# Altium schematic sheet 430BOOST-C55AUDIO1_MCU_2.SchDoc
size A4
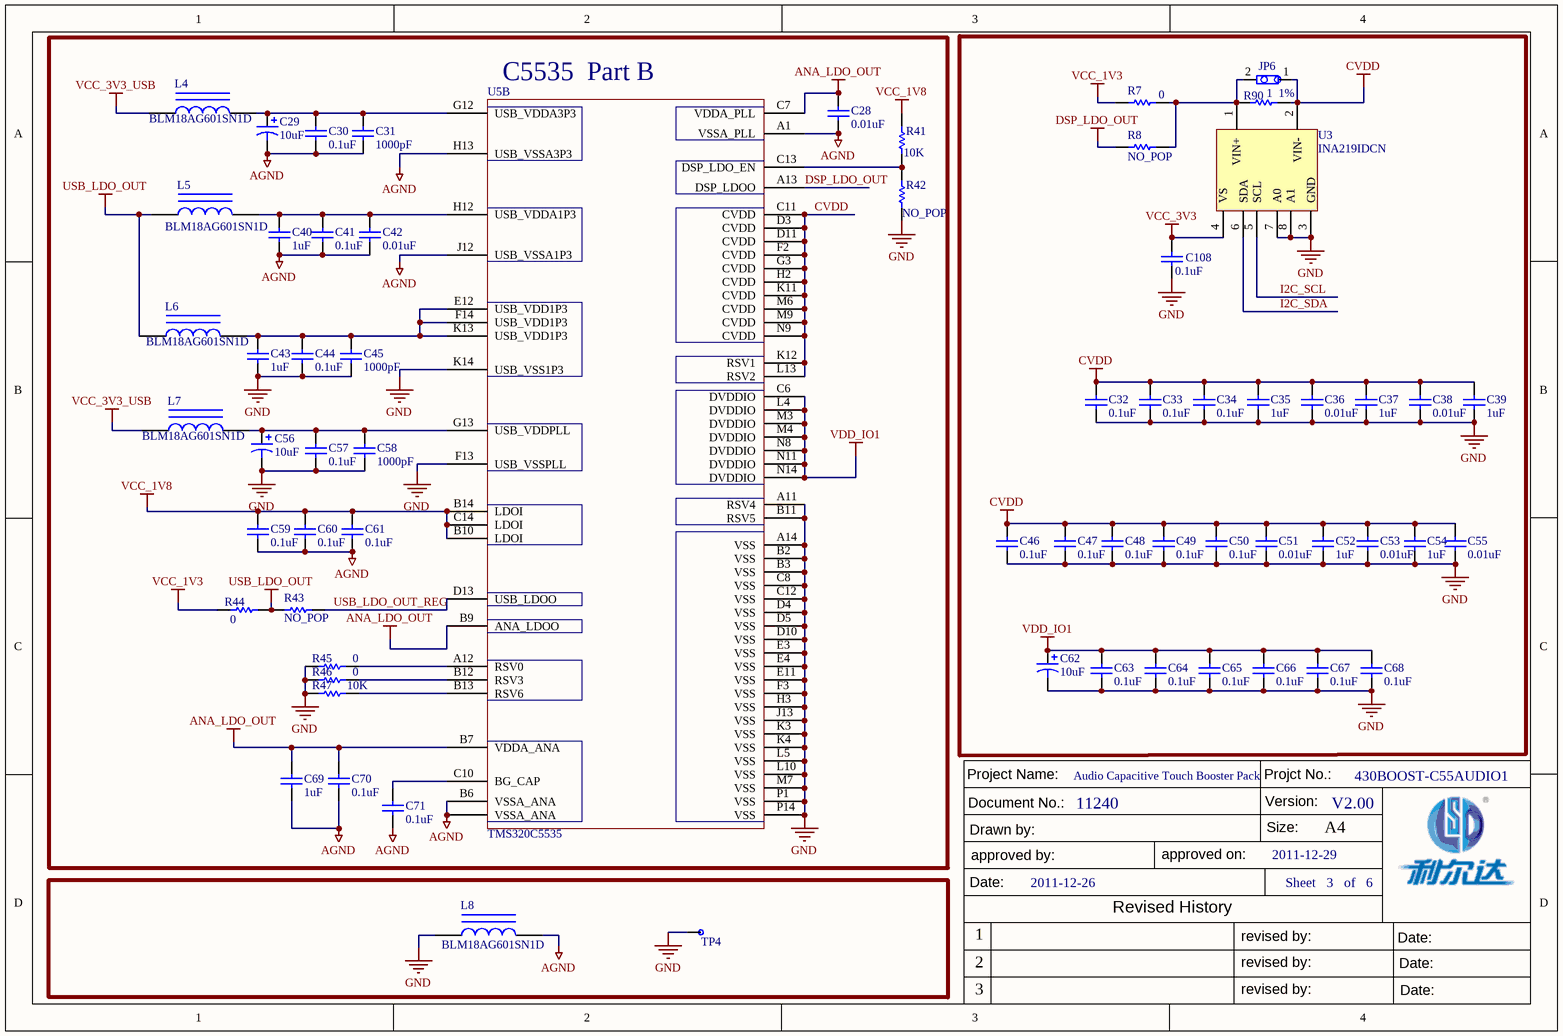
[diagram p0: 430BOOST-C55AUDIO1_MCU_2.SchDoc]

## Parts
C28  0.01uF  [0402-C]
C29  10uF  [0805-C]
C30  0.1uF  [0402-C]
C31  1000pF  [0402-C]
C32  0.1uF  [0402-C]
C33  0.1uF  [0402-C]
C34  0.1uF  [0402-C]
C35  1uF  [0603-C]
C36  0.01uF  [0402-C]
C37  1uF  [0603-C]
C38  0.01uF  [0402-C]
C39  1uF  [0603-C]
C40  1uF  [0603-C]
C41  0.1uF  [0402-C]
C42  0.01uF  [0402-C]
C43  1uF  [0603-C]
C44  0.1uF  [0402-C]
C45  1000pF  [0402-C]
C46  0.1uF  [0402-C]
C47  0.1uF  [0402-C]
C48  0.1uF  [0402-C]
C49  0.1uF  [0402-C]
C50  0.1uF  [0402-C]
C51  0.01uF  [0402-C]
C52  1uF  [0603-C]
C53  0.01uF  [0402-C]
C54  1uF  [0603-C]
C55  0.01uF  [0402-C]
C56  10uF  [0805-C]
C57  0.1uF  [0402-C]
C58  1000pF  [0402-C]
C59  0.1uF  [0402-C]
C60  0.1uF  [0402-C]
C61  0.1uF  [0402-C]
C62  10uF  [0805-C]
C63  0.1uF  [0402-C]
C64  0.1uF  [0402-C]
C65  0.1uF  [0402-C]
C66  0.1uF  [0402-C]
C67  0.1uF  [0402-C]
C68  0.1uF  [0402-C]
C69  1uF  [0603-C]
C70  0.1uF  [0402-C]
C71  0.1uF  [0402-C]
C108  0.1uF  [0402-C]
JP6  (no value)  [SIP2-2.54]
L4  BLM18AG601SN1D  [0603-L]
L5  BLM18AG601SN1D  [0603-L]
L6  BLM18AG601SN1D  [0603-L]
L7  BLM18AG601SN1D  [0603-L]
L8  BLM18AG601SN1D  [0603-L]
R7  0  [0402-R]
R8  NO_POP  [0402-R]
R41  10K  [0402-R]
R42  NO_POP  [0402-R]
R43  NO_POP  [0402-R]
R44  0  [0402-R]
R45  0  [0402-R]
R46  0  [0402-R]
R47  10K  [0402-R]
R90  1  1%  [0402-R]
TP4  GND  [SIP1-TEST]  (value not drawn)
U3  INA219IDCN  [SOT-23-8P]
U5  TMS320C5535  [BGA-N144-0.8MM]  (part B of 2)

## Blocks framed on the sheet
C5535  Part B: C28-C31 C40-C45 C56-C61 C69-C71 L4-L7 R41-R47 U5

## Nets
AGND: C28.1 C29.2 C30.1 C31.1 C40.1 C41.1 C42.1 C59.1 C60.1 C61.1 C69.1 C70.1 C71.1 L8.2 U5.?1(VSSA_ANA) U5.A1(VSSA_PLL) U5.B6(VSSA_ANA) U5.H13(USB_VSSA3P3) U5.J12(USB_VSSA1P3)
ANA_LDO_OUT: C28.2 C69.2 C70.2 U5.B7(VDDA_ANA) U5.B9(ANA_LDOO) U5.C7(VDDA_PLL)
CVDD: C32.2 C33.2 C34.2 C35.2 C36.2 C37.2 C38.2 C39.2 C46.2 C47.2 C48.2 C49.2 C50.2 C51.2 C52.2 C53.2 C54.2 C55.2 JP6.1 R90.2 U3.2(VIN-) U5.C11(CVDD) U5.D3(CVDD) U5.D11(CVDD) U5.F2(CVDD) U5.G3(CVDD) U5.H2(CVDD) U5.K11(CVDD) U5.K12(RSV1) U5.L13(RSV2) U5.M6(CVDD) U5.M9(CVDD) U5.N9(CVDD)
DSP_LDO_OUT: R8.1 U5.A13(DSP_LDOO)
GND: C32.1 C33.1 C34.1 C35.1 C36.1 C37.1 C38.1 C39.1 C43.1 C44.1 C45.1 C46.1 C47.1 C48.1 C49.1 C50.1 C51.1 C52.1 C53.1 C54.1 C55.1 C56.2 C57.1 C58.1 C62.2 C63.1 C64.1 C65.1 C66.1 C67.1 C68.1 C108.1 L8.1 R42.1 R45.2 R46.2 R47.2 TP4.1 U3.3(GND) U3.7(A0) U3.8(A1) U5.A11(RSV4) U5.A14(VSS) U5.B2(VSS) U5.B3(VSS) U5.B11(RSV5) U5.C8(VSS) U5.C12(VSS) U5.D4(VSS) U5.D5(VSS) U5.D10(VSS) U5.E3(VSS) U5.E4(VSS) U5.E11(VSS) U5.F3(VSS) U5.F13(USB_VSSPLL) U5.H3(VSS) U5.J13(VSS) U5.K3(VSS) U5.K4(VSS) U5.K14(USB_VSS1P3) U5.L5(VSS) U5.L10(VSS) U5.M7(VSS) U5.P1(VSS) U5.P14(VSS)
USB_LDO_OUT: L5.1 L6.1 R43.1 R44.2
VCC_1V3: R7.1 R44.1
VCC_1V8: C59.2 C60.2 C61.2 R41.2 U5.B10(LDOI) U5.B14(LDOI) U5.C14(LDOI)
VCC_3V3: C108.2 U3.4(VS)
VCC_3V3_USB: L4.1 L7.1
VDD_IO1: C62.1 C63.2 C64.2 C65.2 C66.2 C67.2 C68.2 U5.C6(DVDDIO) U5.L4(DVDDIO) U5.M3(DVDDIO) U5.M4(DVDDIO) U5.N8(DVDDIO) U5.N11(DVDDIO) U5.N14(DVDDIO)
I2C_SCL: U3.5(SCL)
I2C_SDA: U3.6(SDA)
USB_LDO_OUT_REG: R43.2 U5.D13(USB_LDOO)
NetC29_1: C29.1 C30.2 C31.2 L4.2 U5.G12(USB_VDDA3P3)
NetC40_2: C40.2 C41.2 C42.2 L5.2 U5.H12(USB_VDDA1P3)
NetC43_2: C43.2 C44.2 C45.2 L6.2 U5.E12(USB_VDD1P3) U5.F14(USB_VDD1P3) U5.K13(USB_VDD1P3)
NetC56_1: C56.1 C57.2 C58.2 L7.2 U5.G13(USB_VDDPLL)
NetC71_2: C71.2 U5.C10(BG_CAP)
NetJP6_2: JP6.2 R7.2 R8.2 R90.1 U3.1(VIN+)
NetR41_1: R41.1 R42.2 U5.C13(DSP_LDO_EN)
NetR45_1: R45.1 U5.A12(RSV0)
NetR46_1: R46.1 U5.B12(RSV3)
NetR47_1: R47.1 U5.B13(RSV6)

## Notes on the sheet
- Audio Capacitive Touch Booster Pack
- 430BOOST-C55AUDIO1
- 11240
- V2.00
- 2011-12-26
- 2011-12-29
- Sheet   3   of   6

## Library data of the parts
C28 C30-C55 C57-C61 C63-C71 C108 = Cap: Capacitor; Value: 100pF
C29 C56 C62 = Cap Pol1: Polarized Capacitor (Radial); Value: 100pF
JP6 = JUMPER
L4-L8 = Inductor Iron: Magnetic-Core Inductor; Value: 10mH
R7 R8 R41-R47 R90 = Res1: Resistor; Value: 1K
TP4 = TextPoint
